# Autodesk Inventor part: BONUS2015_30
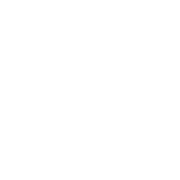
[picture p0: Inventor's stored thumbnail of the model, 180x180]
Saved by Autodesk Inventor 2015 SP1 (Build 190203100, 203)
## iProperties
Created: 2015-05
Part Number: BONUS2015_30
Material: Generisch
Document SubType Name: Modeling
Density: 1 g/cm^3
Appearance: Vorgabe
xx: 30
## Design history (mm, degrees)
